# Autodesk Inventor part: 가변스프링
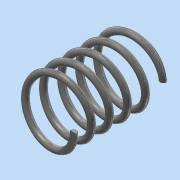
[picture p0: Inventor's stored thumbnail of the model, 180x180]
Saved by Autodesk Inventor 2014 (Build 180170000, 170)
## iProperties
Created: 2024-02
Part Number: 가변스프링
Material: 스테인레스 스틸
Document SubType Name: Modeling
Designer: dg
Density: 8.08 g/cm^3
Appearance: 반연마
Mass: 7.07161 g
Surface Area: 17.7587 cm^2
Volume: 0.875199 cm^3
Author: dg
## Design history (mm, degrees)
sketch "스케치1"
  geometry: L1 (9, 0)-(0, 0); L2 (0, 0)-(0, 28.5); L3 (0, 28.5)-(9, 28.5); C1 r 1 at (9, 0)
  constraints: 6 end point, 2 parallel, 1 centre point, 1 coincident, 1 horizontal, 1 perpendicular
  dimensions: "d0" = 2 diameter of C1; "d1" = 18 diameter of L1.start L2; "d2" = 28.5 distance of L1.end L2.end (derived)
feature "코일1" sketch "스케치1" pitch "d3" = 10; turns "d5" = 5; dims "d4" = 28.49992 (computed from d2), "d6" = 0, angle "d7" = 90 deg, angle "d8" = 90 deg, "d9" = 0, "d10" = 0
node "작업 평면1"
feature "분할1"
feature "분할2"
node "솔리드1"
other parameters: "d11" = 0
